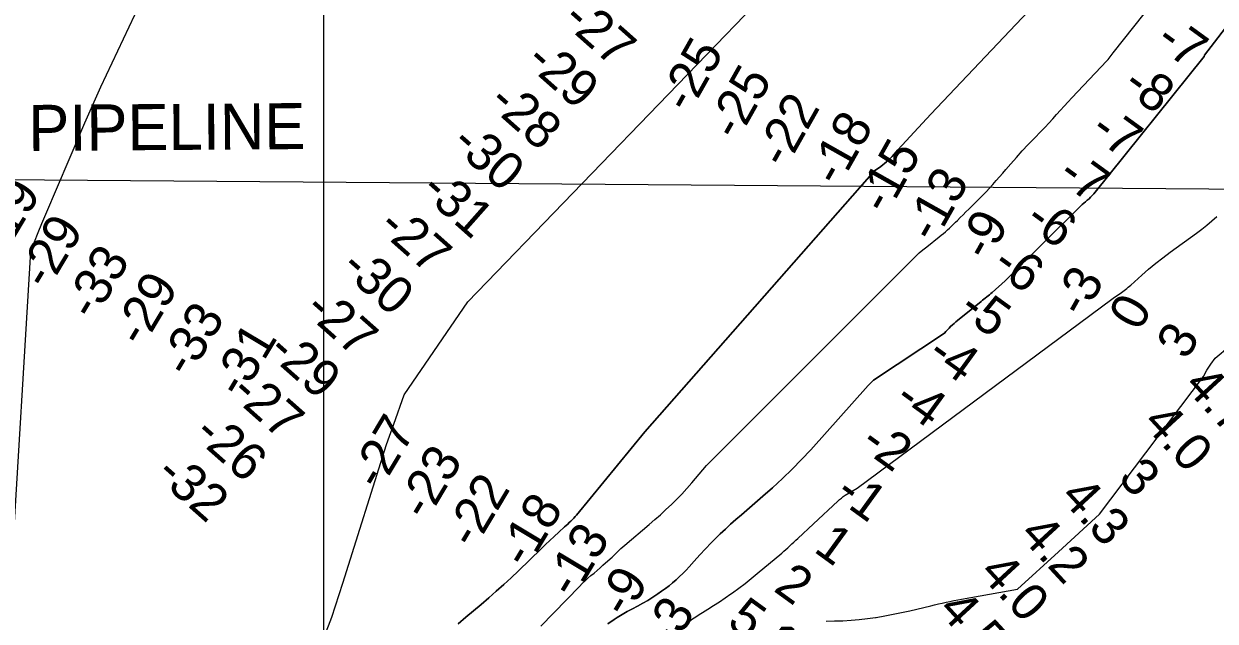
# Model space of a CAD drawing. Extents: x 3271442 to 3309282, y 752266 to 777610.
# Drawn here: x 3290779 to 3292928, y 765032 to 766109 of the extents above; entities that cross this region are included whole.
import ezdxf

# ---------------------------------------------------------------- set-up
doc = ezdxf.new("R2010")
doc.units = 0
for name, color, linetype in [('V-GRID-MAJR', 7, 'Continuous'), ('V-RIVR-RANG', 7, 'Continuous'), ('V-TOPO-DPTH', 7, 'Continuous'), ('V-TOPO-MINR', 7, 'Continuous'), ('V-TOPO-WATR', 7, 'Continuous'), ('V-UTIL-IDEN', 7, 'Continuous'), ('V-UTIL-LINE', 7, 'Continuous')]:
    doc.layers.add(name, color=color, linetype=linetype)

msp = doc.modelspace()

# ---------------------------------------------------------------- linework, layer by layer
at = {"layer": 'V-GRID-MAJR'}
msp.add_spline([(3291322.7, 757646.2), (3291320.9, 763704.7), (3291319.2, 769766.6), (3291317.4, 775828.6), (3291317.4, 775832)], degree=3, dxfattribs=at)
at = {"layer": 'V-TOPO-DPTH'}
for points in [[(3292914.5, 766405.3), (3292909.4, 766401.1), (3292902.2, 766396.3), (3292894.8, 766391.8), (3292890.1, 766389.2), (3292880.5, 766383.2), (3292871.3, 766376.7), (3292601.9, 766143.6), (3292596.1, 766137.7), (3292590.4, 766131.7), (3292415, 765946.1), (3292400.1, 765930.2), (3292385.2, 765914.2), (3292370.5, 765898.2), (3292355.8, 765882), (3292345.2, 765870.3), (3292335.4, 765860.7), (3292324.9, 765851.8), (3292313.6, 765844.3), (3291899.4, 765373.9)], [(3292914.5, 766405.3), (3292909.4, 766401.1), (3292902.2, 766396.3), (3292894.8, 766391.8), (3292890.1, 766389.2), (3292880.5, 766383.2), (3292871.3, 766376.7), (3292601.9, 766143.6), (3292596.1, 766137.7), (3292590.4, 766131.7), (3292415, 765946.1), (3292400.1, 765930.2), (3292385.2, 765914.2), (3292370.5, 765898.2), (3292355.8, 765882), (3292345.2, 765870.3), (3292335.4, 765860.7), (3292324.9, 765851.8), (3292313.6, 765844.3), (3291899.4, 765373.9)], [(3291446.6, 765387.6), (3291465.3, 765440.4), (3291580, 765607.9), (3292148.5, 766196.6)], [(3291446.6, 765387.6), (3291465.3, 765440.4), (3291580, 765607.9), (3292148.5, 766196.6)], [(3292112.4, 765257.7), (3292129.6, 765273), (3292147.5, 765289.4), (3292165.1, 765306.2), (3292182, 765323.7), (3292198.6, 765341.5), (3292302.2, 765457.2), (3292305.4, 765460.5), (3292308.6, 765463.7), (3292312, 765466.7), (3292439.6, 765551.4), (3292442.3, 765554.5), (3292445.1, 765557.6), (3292448, 765560.6), (3292450.9, 765563.6), (3292454, 765566.4), (3292457, 765569.2), (3292460.2, 765571.9), (3292463.4, 765574.6), (3292506.1, 765608.9), (3292508.5, 765610.9), (3292511, 765612.9), (3292513.4, 765614.9), (3292515.9, 765616.9), (3292518.3, 765618.9), (3292520.7, 765620.9), (3292523.1, 765623), (3292525.5, 765625.1), (3292549, 765645.9), (3292687.9, 765783.3), (3292691.1, 765785.8), (3292694.3, 765788.4), (3292697.4, 765791.1), (3292700.5, 765793.8), (3292703.4, 765796.7), (3292706.3, 765799.6), (3292709.1, 765802.6), (3292908.2, 766050.4), (3292908.8, 766052.6), (3293020.6, 766198.6)], [(3293020.6, 766198.6), (3292908.8, 766052.6), (3292908.2, 766050.4), (3292709.1, 765802.6), (3292706.3, 765799.6), (3292703.4, 765796.7), (3292700.5, 765793.8), (3292697.4, 765791.1), (3292694.3, 765788.4), (3292691.1, 765785.8), (3292687.9, 765783.3), (3292549, 765645.9), (3292525.5, 765625.1), (3292523.1, 765623), (3292520.7, 765620.9), (3292518.3, 765618.9), (3292515.9, 765616.9), (3292513.4, 765614.9), (3292511, 765612.9), (3292508.5, 765610.9), (3292506.1, 765608.9), (3292463.4, 765574.6), (3292460.2, 765571.9), (3292457, 765569.2), (3292454, 765566.4), (3292450.9, 765563.6), (3292448, 765560.6), (3292445.1, 765557.6), (3292442.3, 765554.5), (3292439.6, 765551.4), (3292312, 765466.7), (3292308.6, 765463.7), (3292305.4, 765460.5), (3292302.2, 765457.2), (3292198.6, 765341.5), (3292182, 765323.7), (3292165.1, 765306.2), (3292147.5, 765289.4), (3292129.6, 765273), (3292112.4, 765257.7)], [(3290978.8, 766124.7), (3290948, 766060.2), (3290917.9, 765995.3), (3290888.7, 765929.9), (3290887.1, 765926.1)], [(3290978.8, 766124.7), (3290948, 766060.2), (3290917.9, 765995.3), (3290888.7, 765929.9), (3290887.1, 765926.1)], [(3292457.2, 765069.6), (3292463.7, 765070.9), (3292470.7, 765072.2), (3292571.7, 765090.1), (3292645.4, 765157.7), (3292719.2, 765225.2), (3292906.9, 765473.6), (3292913.2, 765485), (3292920.2, 765496), (3292928.2, 765506.3), (3293005.8, 765571.3), (3293098.1, 765670.8), (3293100.5, 765673.5), (3293103.1, 765676), (3293105.7, 765678.5), (3293108.5, 765680.7), (3293454, 765903.5), (3293430.7, 766002.5)], [(3292457.2, 765069.6), (3292463.7, 765070.9), (3292470.7, 765072.2), (3292571.7, 765090.1), (3292645.4, 765157.7), (3292719.2, 765225.2), (3292906.9, 765473.6), (3292913.2, 765485), (3292920.2, 765496), (3292928.2, 765506.3), (3293005.8, 765571.3), (3293098.1, 765670.8), (3293100.5, 765673.5), (3293103.1, 765676), (3293105.7, 765678.5), (3293108.5, 765680.7), (3293454, 765903.5), (3293430.7, 766002.5)], [(3290887.1, 765926.1), (3290860.3, 765864.3), (3290818.3, 765765.4), (3290811.4, 765748.9), (3290804.7, 765732.4), (3290798.1, 765715.8), (3290791.6, 765699.1), (3290757.2, 765130.7)], [(3290887.1, 765926.1), (3290860.3, 765864.3), (3290818.3, 765765.4), (3290811.4, 765748.9), (3290804.7, 765732.4), (3290798.1, 765715.8), (3290791.6, 765699.1), (3290757.2, 765130.7)], [(3291311.4, 764979.3), (3291334.7, 765039.6), (3291354.8, 765101.2), (3291433.3, 765350.8), (3291446.6, 765387.6)], [(3291311.4, 764979.3), (3291334.7, 765039.6), (3291354.8, 765101.2), (3291433.3, 765350.8), (3291446.6, 765387.6)], [(3291899.4, 765373.9), (3291775.9, 765223.8), (3291773.5, 765220.9), (3291771, 765218.1), (3291768.4, 765215.4), (3291765.7, 765212.7), (3291763, 765210.1), (3291760.2, 765207.5), (3291757.5, 765204.9), (3291754.7, 765202.4), (3291744.1, 765192.7), (3291736.1, 765185.3), (3291728.1, 765177.9), (3291720.1, 765170.4), (3291712.2, 765162.8), (3291671.3, 765123.3), (3291658.2, 765110.8), (3291645, 765098.5), (3291631.5, 765086.4), (3291618, 765074.5), (3291604.3, 765062.7), (3291590.5, 765051), (3291576.7, 765039.4), (3291562.8, 765027.8)], [(3291899.4, 765373.9), (3291775.9, 765223.8), (3291773.5, 765220.9), (3291771, 765218.1), (3291768.4, 765215.4), (3291765.7, 765212.7), (3291763, 765210.1), (3291760.2, 765207.5), (3291757.5, 765204.9), (3291754.7, 765202.4), (3291744.1, 765192.7), (3291736.1, 765185.3), (3291728.1, 765177.9), (3291720.1, 765170.4), (3291712.2, 765162.8), (3291671.3, 765123.3), (3291658.2, 765110.8), (3291645, 765098.5), (3291631.5, 765086.4), (3291618, 765074.5), (3291604.3, 765062.7), (3291590.5, 765051), (3291576.7, 765039.4), (3291562.8, 765027.8)], [(3291832.8, 765027.7), (3291844.1, 765035.5), (3291849.4, 765038.9), (3291858.4, 765044.5), (3291867.5, 765049.9), (3291876.9, 765055), (3291886.3, 765059.8), (3291895.6, 765064.8), (3291904.9, 765070), (3291913.8, 765075.6), (3291922.7, 765081.5), (3291929.6, 765086.4), (3291936.4, 765091.3), (3291943, 765096.4), (3291949.4, 765101.7), (3291955.8, 765107.1), (3291961.9, 765112.8), (3291967.9, 765118.6), (3291973.7, 765124.6), (3291979.4, 765130.7), (3291988.3, 765140.7), (3291998.4, 765151.8), (3292008.7, 765162.8), (3292019.2, 765173.5), (3292029.8, 765184.2), (3292035.4, 765189.7), (3292044.7, 765198.6), (3292054.1, 765207.3), (3292063.7, 765215.8), (3292073.4, 765224.2), (3292083.3, 765232.5), (3292093, 765240.8), (3292102.7, 765249.2), (3292112.4, 765257.7), (3292112.4, 765257.7)], [(3292112.4, 765257.7), (3292112.4, 765257.7), (3292102.7, 765249.2), (3292093, 765240.8), (3292083.3, 765232.5), (3292073.4, 765224.2), (3292063.7, 765215.8), (3292054.1, 765207.3), (3292044.7, 765198.6), (3292035.4, 765189.7), (3292029.8, 765184.2), (3292019.2, 765173.5), (3292008.7, 765162.8), (3291998.4, 765151.8), (3291988.3, 765140.7), (3291979.4, 765130.7), (3291973.7, 765124.6), (3291967.9, 765118.6), (3291961.9, 765112.8), (3291955.8, 765107.1), (3291949.4, 765101.7), (3291943, 765096.4), (3291936.4, 765091.3), (3291929.6, 765086.4), (3291922.7, 765081.5), (3291913.8, 765075.6), (3291904.9, 765070), (3291895.6, 765064.8), (3291886.3, 765059.8), (3291876.9, 765055), (3291867.5, 765049.9), (3291858.4, 765044.5), (3291849.4, 765038.9), (3291844.1, 765035.5), (3291832.8, 765027.7)], [(3292226.6, 765032.3), (3292241.5, 765032.8), (3292256.4, 765033.3), (3292271.2, 765034.1), (3292286, 765035.3), (3292300.8, 765037.1), (3292315.5, 765039.1), (3292316.8, 765039.3), (3292332, 765041.9), (3292347.3, 765044.8), (3292362.4, 765048), (3292377.5, 765051.4), (3292414.9, 765060.4), (3292421.8, 765062), (3292428.8, 765063.6), (3292435.7, 765065.2), (3292442.7, 765066.7), (3292449.7, 765068.1), (3292456.7, 765069.5), (3292457.2, 765069.6)], [(3292226.6, 765032.3), (3292241.5, 765032.8), (3292256.4, 765033.3), (3292271.2, 765034.1), (3292286, 765035.3), (3292300.8, 765037.1), (3292315.5, 765039.1), (3292316.8, 765039.3), (3292332, 765041.9), (3292347.3, 765044.8), (3292362.4, 765048), (3292377.5, 765051.4), (3292414.9, 765060.4), (3292421.8, 765062), (3292428.8, 765063.6), (3292435.7, 765065.2), (3292442.7, 765066.7), (3292449.7, 765068.1), (3292456.7, 765069.5), (3292457.2, 765069.6)]]:
    msp.add_lwpolyline(points, dxfattribs=at)
at = {"layer": 'V-TOPO-MINR'}
for points in [[(3291899.4, 765373.9), (3292313.6, 765844.3), (3292324.9, 765851.8), (3292335.4, 765860.7), (3292345.2, 765870.3), (3292355.8, 765882), (3292370.5, 765898.2), (3292385.2, 765914.2), (3292400.1, 765930.2), (3292415, 765946.1), (3292590.4, 766131.7), (3292596.1, 766137.7), (3292601.9, 766143.6), (3292871.3, 766376.7), (3292880.5, 766383.2), (3292890.1, 766389.2), (3292894.8, 766391.8), (3292902.2, 766396.3), (3292909.4, 766401.1), (3292914.5, 766405.3)], [(3291446.6, 765387.6), (3291465.3, 765440.4), (3291580, 765607.9), (3292148.5, 766196.6)], [(3292112.4, 765257.7), (3292129.6, 765273), (3292147.5, 765289.4), (3292165.1, 765306.2), (3292182, 765323.7), (3292198.6, 765341.5), (3292302.2, 765457.2), (3292305.4, 765460.5), (3292308.6, 765463.7), (3292312, 765466.7), (3292439.6, 765551.4), (3292442.3, 765554.5), (3292445.1, 765557.6), (3292448, 765560.6), (3292450.9, 765563.6), (3292454, 765566.4), (3292457, 765569.2), (3292460.2, 765571.9), (3292463.4, 765574.6), (3292506.1, 765608.9), (3292508.5, 765610.9), (3292511, 765612.9), (3292513.4, 765614.9), (3292515.9, 765616.9), (3292518.3, 765618.9), (3292520.7, 765620.9), (3292523.1, 765623), (3292525.5, 765625.1), (3292549, 765645.9), (3292687.9, 765783.3), (3292691.1, 765785.8), (3292694.3, 765788.4), (3292697.4, 765791.1), (3292700.5, 765793.8), (3292703.4, 765796.7), (3292706.3, 765799.6), (3292709.1, 765802.6), (3292908.2, 766050.4), (3292908.8, 766052.6), (3293020.6, 766198.6)], [(3292010.6, 765313.2), (3292394.2, 765696.4), (3292401, 765701.8), (3292407.9, 765707.3), (3292430.1, 765725), (3292433.9, 765728.1), (3292437.8, 765731.3), (3292441.6, 765734.5), (3292445.4, 765737.8), (3292449.1, 765741.1), (3292452.7, 765744.5), (3292456.3, 765747.9), (3292459.8, 765751.4), (3292463.1, 765754.8), (3292468.2, 765760), (3292473.4, 765765.1), (3292478.5, 765770.3), (3292483.7, 765775.4), (3292502.4, 765793.7), (3292508.7, 765800.1), (3292514.9, 765806.5), (3292521, 765813.1), (3292527, 765819.8), (3292532.9, 765826.6), (3292538.9, 765833.3), (3292544.8, 765840.1), (3292550.7, 765846.9), (3292559.3, 765856.8), (3292569.7, 765868.5), (3292580.1, 765880.1), (3292590.8, 765891.5), (3292601.6, 765902.7), (3292614, 765915.5), (3292621.2, 765922.9), (3292628.2, 765930.4), (3292635.1, 765938), (3292642, 765945.6), (3292648.8, 765953.3), (3292655.7, 765960.9), (3292662.7, 765968.5), (3292669.7, 765976), (3292732.6, 766042.5), (3292734.7, 766044.8), (3292736.7, 766047.2), (3292738.7, 766049.6), (3292740.6, 766052), (3292742.4, 766054.6), (3292744, 766057.2), (3292837, 766174.8)], [(3290978.8, 766124.7), (3290948, 766060.2), (3290917.9, 765995.3), (3290888.7, 765929.9), (3290887.1, 765926.1)], [(3290887.1, 765926.1), (3290860.3, 765864.3), (3290818.3, 765765.4), (3290811.4, 765748.9), (3290804.7, 765732.4), (3290798.1, 765715.8), (3290791.6, 765699.1), (3290757.2, 765130.7)], [(3292203.7, 765207.9), (3292247.3, 765248.6), (3292248.9, 765250.1), (3292250.5, 765251.5), (3292252.2, 765252.9), (3292253.8, 765254.3), (3292255.5, 765255.6), (3292257.2, 765256.9), (3292259, 765258.1), (3292260.8, 765259.3), (3292282, 765272), (3292741.5, 765612.8), (3292746.6, 765616.6), (3292756.4, 765623.3), (3292758.9, 765625), (3292761.4, 765626.8), (3292763.9, 765628.6), (3292766.3, 765630.5), (3292768.6, 765632.4), (3292771, 765634.4), (3292773.3, 765636.4), (3292775.6, 765638.4), (3292795.6, 765656.2), (3292808, 765667), (3292820.7, 765677.5), (3292833.7, 765687.6), (3292846.8, 765697.4), (3292894.3, 765731.7), (3292903.8, 765738.9), (3292913.1, 765746.2), (3292922.2, 765753.9), (3292931.1, 765761.8)], [(3291311.4, 764979.3), (3291334.7, 765039.6), (3291354.8, 765101.2), (3291433.3, 765350.8), (3291446.6, 765387.6)], [(3291562.8, 765027.8), (3291576.7, 765039.4), (3291590.5, 765051), (3291604.3, 765062.7), (3291618, 765074.5), (3291631.5, 765086.4), (3291645, 765098.5), (3291658.2, 765110.8), (3291671.3, 765123.3), (3291712.2, 765162.8), (3291720.1, 765170.4), (3291728.1, 765177.9), (3291736.1, 765185.3), (3291744.1, 765192.7), (3291754.7, 765202.4), (3291757.5, 765204.9), (3291760.2, 765207.5), (3291763, 765210.1), (3291765.7, 765212.7), (3291768.4, 765215.4), (3291771, 765218.1), (3291773.5, 765220.9), (3291775.9, 765223.8), (3291899.4, 765373.9)], [(3291711.8, 765023.5), (3291781.3, 765095), (3291786.3, 765100.1), (3291791.5, 765105), (3291796.8, 765109.8), (3291802.2, 765114.5), (3291807.7, 765119.1), (3291813.1, 765123.8), (3291818.5, 765128.5), (3291823.8, 765133.2), (3291836.9, 765144.9), (3291840.3, 765148), (3291843.5, 765151), (3291846.7, 765154.1), (3291849.9, 765157.3), (3291853.1, 765160.4), (3291856.3, 765163.5), (3291859.7, 765166.5), (3291863, 765169.5), (3291907, 765206.7), (3291917.2, 765215.5), (3291927.4, 765224.4), (3291937.3, 765233.5), (3291947.2, 765242.7), (3291956.8, 765252.1), (3291966.2, 765261.7), (3291975.3, 765271.6), (3291984.1, 765281.8), (3292010.6, 765313.2)], [(3291832.8, 765027.7), (3291844.1, 765035.5), (3291849.4, 765038.9), (3291858.4, 765044.5), (3291867.5, 765049.9), (3291876.9, 765055), (3291886.3, 765059.8), (3291895.6, 765064.8), (3291904.9, 765070), (3291913.8, 765075.6), (3291922.7, 765081.5), (3291929.6, 765086.4), (3291936.4, 765091.3), (3291943, 765096.4), (3291949.4, 765101.7), (3291955.8, 765107.1), (3291961.9, 765112.8), (3291967.9, 765118.6), (3291973.7, 765124.6), (3291979.4, 765130.7), (3291988.3, 765140.7), (3291998.4, 765151.8), (3292008.7, 765162.8), (3292019.2, 765173.5), (3292029.8, 765184.2), (3292035.4, 765189.7), (3292044.7, 765198.6), (3292054.1, 765207.3), (3292063.7, 765215.8), (3292073.4, 765224.2), (3292083.3, 765232.5), (3292093, 765240.8), (3292102.7, 765249.2), (3292112.4, 765257.7), (3292112.4, 765257.7)], [(3291974.5, 765029.3), (3291979.6, 765032.7), (3291985.6, 765036.6), (3291991.5, 765040.4), (3291997.5, 765044.2), (3292003.5, 765048.1), (3292012.7, 765053.9), (3292023.3, 765060.7), (3292033.8, 765067.6), (3292044.2, 765074.6), (3292054.5, 765081.8), (3292057.2, 765083.7), (3292068.7, 765092.1), (3292080, 765100.6), (3292091.2, 765109.4), (3292102.2, 765118.4), (3292146.3, 765155.3), (3292150, 765158.4), (3292153.7, 765161.6), (3292157.4, 765164.9), (3292161, 765168.2), (3292164.6, 765171.6), (3292168.2, 765174.9), (3292171.8, 765178.2), (3292175.4, 765181.6), (3292203.7, 765207.9)]]:
    msp.add_lwpolyline(points, dxfattribs=at)
at = {"layer": 'V-TOPO-WATR'}
for points in [[(3292457.2, 765069.6), (3292463.7, 765070.9), (3292470.7, 765072.2), (3292571.7, 765090.1), (3292645.4, 765157.7), (3292719.2, 765225.2), (3292906.9, 765473.6), (3292913.2, 765485), (3292920.2, 765496), (3292928.2, 765506.3), (3293005.8, 765571.3), (3293098.1, 765670.8), (3293100.5, 765673.5), (3293103.1, 765676), (3293105.7, 765678.5), (3293108.5, 765680.7), (3293454, 765903.5), (3293430.7, 766002.5)], [(3292226.6, 765032.3), (3292241.5, 765032.8), (3292256.4, 765033.3), (3292271.2, 765034.1), (3292286, 765035.3), (3292300.8, 765037.1), (3292315.5, 765039.1), (3292316.8, 765039.3), (3292332, 765041.9), (3292347.3, 765044.8), (3292362.4, 765048), (3292377.5, 765051.4), (3292414.9, 765060.4), (3292421.8, 765062), (3292428.8, 765063.6), (3292435.7, 765065.2), (3292442.7, 765066.7), (3292449.7, 765068.1), (3292456.7, 765069.5), (3292457.2, 765069.6)]]:
    msp.add_lwpolyline(points, dxfattribs=at)
at = {"layer": 'V-UTIL-LINE'}
msp.add_lwpolyline([(3294376.7, 765957.2), (3294160.8, 765801.8), (3289882.4, 765834.6), (3289537.5, 765900.3)], dxfattribs=at)

# ---------------------------------------------------------------- texts
at = {"layer": 'V-RIVR-RANG'}
for s, rotation, p in [('-27', 318.4481, (3291747.8, 766112.8)), ('-7', 324.0391, (3292817.2, 766071.7)), ('-25', 60.5646, (3291979.4, 765945.5)), ('-29', 318.4481, (3291681.5, 766037.9)), ('-25', 60.5646, (3292066.3, 765896.1)), ('-8', 324.0391, (3292757.9, 765991.2)), ('-28', 318.4481, (3291614.4, 765963.8)), ('-22', 60.5646, (3292152.8, 765845.9)), ('-18', 60.5646, (3292249.1, 765813)), ('-7', 324.0391, (3292699.4, 765910.1)), ('-30', 318.4481, (3291547.3, 765889.6)), ('-15', 60.5646, (3292335.5, 765762.8)), ('-7', 324.0391, (3292640.5, 765829.3)), ('-13', 60.5646, (3292421.7, 765712)), ('-19', 59.0885, (3290744.9, 765693)), ('-31', 318.4481, (3291491.9, 765805.1)), ('-29', 59.0885, (3290821.9, 765627)), ('-27', 318.4481, (3291415.3, 765739.4)), ('-9', 60.5646, (3292517.9, 765679)), ('-6', 324.0391, (3292581.5, 765748.5)), ('-33', 59.0885, (3290905.5, 765572)), ('-6', 324.0391, (3292522.6, 765667.7)), ('-30', 318.4481, (3291347.8, 765665.6)), ('-3', 60.5646, (3292690.1, 765577.3)), ('-29', 59.0885, (3290993.2, 765523.8)), ('-33', 59.0885, (3291076.8, 765468.8)), ('-27', 318.4481, (3291282.3, 765590)), ('-5', 324.0391, (3292462.4, 765587.8)), ('0', 60.5646, (3292791.2, 765552.9)), ('3', 60.5646, (3292877, 765501.5)), ('-31', 59.0885, (3291171.3, 765431.9)), ('-29', 318.4481, (3291216, 765515.1)), ('-4', 324.0391, (3292405, 765506)), ('4.7', 312.6506, (3292869.6, 765455.3)), ('-27', 318.4481, (3291149.3, 765440.6)), ('-4', 324.0391, (3292346.1, 765425.2)), ('-27', 59.0885, (3291421.4, 765265.6)), ('4.0', 312.6506, (3292795.3, 765388.3)), ('-26', 318.4481, (3291082.8, 765366)), ('-2', 324.0391, (3292284.8, 765346.1)), ('-23', 59.0885, (3291505.5, 765211.3)), ('-32', 318.4481, (3291013.9, 765293.4)), ('3', 312.6506, (3292751.1, 765288.7)), ('-22', 59.0885, (3291591.4, 765160.2)), ('-18', 59.0885, (3291686.8, 765124.9)), ('-1', 324.0391, (3292239.3, 765255.5)), ('4.3', 312.6506, (3292646.3, 765254.9)), ('-13', 59.0885, (3291771.1, 765071.1)), ('1', 324.0391, (3292201.8, 765159.2)), ('4.2', 312.6506, (3292572.9, 765187)), ('2', 324.0391, (3292129.4, 765088.2)), ('4.0', 312.6506, (3292500.4, 765118)), ('-9', 59.0885, (3291866.4, 765035.6)), ('-3', 59.0885, (3291950.3, 764981)), ('5.1', 324.0391, (3292045.1, 765025.8)), ('4.5', 312.6506, (3292426.2, 765051.1))]:
    msp.add_text(s, height=67, rotation=rotation, dxfattribs=at).set_placement(p)
at = {"layer": 'V-UTIL-IDEN'}
msp.add_text('PIPELINE', height=83, rotation=0.4006, dxfattribs=at).set_placement((3290787.7, 765880))

doc.saveas('drawing.dxf')
